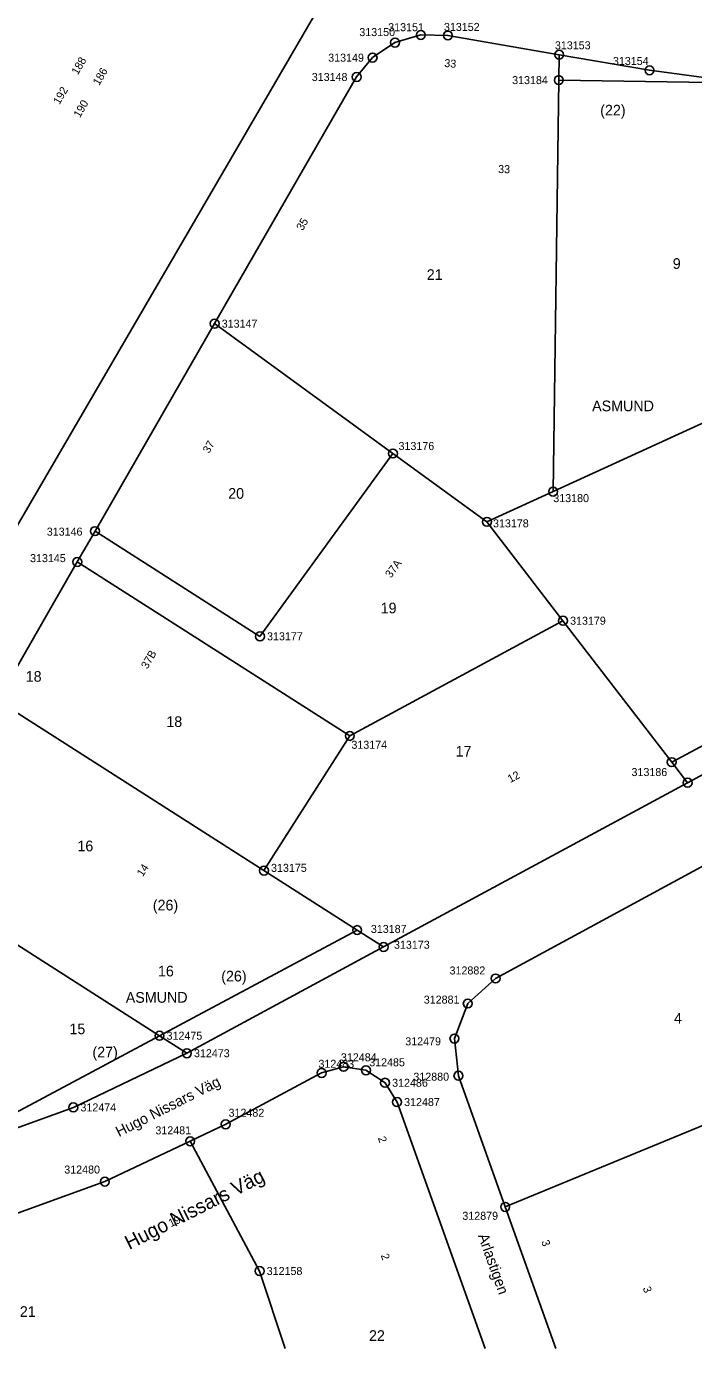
# Model space of a CAD drawing. Extents: x 141995 to 152570, y 6580184 to 6586000.
# Drawn here: x 142544.1 to 142619.1, y 6585000 to 6585148.7 of the extents above; entities that cross this region are included whole.
import ezdxf

# ---------------------------------------------------------------- set-up
doc = ezdxf.new("R2010")
doc.units = 0
for name, color, linetype in [('Level 10', 7, 'Continuous'), ('Level 40', 7, 'Continuous'), ('Level 42', 7, 'Continuous'), ('Level 43', 7, 'Continuous'), ('Level 5', 7, 'Continuous'), ('Level 50', 7, 'Continuous'), ('Level 51', 7, 'Continuous'), ('Level 52', 7, 'Continuous'), ('Level 53', 7, 'Continuous'), ('Level 54', 7, 'Continuous'), ('Level 55', 7, 'Continuous'), ('Level 58', 7, 'Continuous'), ('Level 59', 7, 'Continuous'), ('Level 6', 7, 'Continuous'), ('Level 60', 7, 'Continuous'), ('Level 7', 7, 'Continuous'), ('Level 9', 7, 'Continuous')]:
    doc.layers.add(name, color=color, linetype=linetype)

msp = doc.modelspace()

# ---------------------------------------------------------------- linework, layer by layer
at = {"layer": 'Level 10'}
for centre in [(142585.56, 6585146.87), (142588.47, 6585147.73), (142591.51, 6585147.67), (142583.04, 6585145.18), (142604.03, 6585145.51), (142614.19, 6585143.75), (142581.25, 6585143), (142603.99, 6585142.65), (142565.27, 6585115.26), (142585.33, 6585100.66), (142603.35, 6585096.37), (142551.82, 6585091.93), (142595.91, 6585092.97), (142549.82, 6585088.46), (142604.46, 6585081.85), (142570.37, 6585080.09), (142580.48, 6585068.9), (142616.69, 6585065.95), (142618.48, 6585063.63), (142570.82, 6585053.75), (142581.31, 6585047.06), (142584.28, 6585045.16), (142596.88, 6585041.62), (142593.75, 6585038.8), (142559.07, 6585035.18), (142592.25, 6585034.86), (142562.15, 6585033.21), (142577.31, 6585030.99), (142579.78, 6585031.69), (142582.3, 6585031.3), (142592.7, 6585030.68), (142584.44, 6585029.89), (142585.79, 6585027.72), (142549.38, 6585027.12), (142566.52, 6585025.22), (142562.52, 6585023.31), (142552.92, 6585018.77), (142597.96, 6585015.93), (142570.33, 6585008.72)]:
    msp.add_circle(centre, 0.5, dxfattribs=at)
at = {"layer": 'Level 5'}
for points in [[(142534.91, 6585078.61), (142586.48, 6585167.12)], [(142585.56, 6585146.87), (142588.47, 6585147.73)], [(142588.47, 6585147.73), (142591.51, 6585147.67)], [(142591.51, 6585147.67), (142604.03, 6585145.51)], [(142583.04, 6585145.18), (142585.56, 6585146.87)], [(142581.25, 6585143), (142583.04, 6585145.18)], [(142604.03, 6585145.51), (142603.99, 6585142.65)], [(142565.27, 6585115.26), (142581.25, 6585143)], [(142603.99, 6585142.65), (142630.81, 6585142.24)], [(142551.82, 6585091.93), (142565.27, 6585115.26)], [(142549.82, 6585088.46), (142551.82, 6585091.93)], [(142540.84, 6585072.88), (142549.82, 6585088.46)], [(142645.02, 6585081.08), (142616.69, 6585065.95)], [(142618.48, 6585063.63), (142616.69, 6585065.95)], [(142584.28, 6585045.16), (142618.48, 6585063.63)], [(142631.51, 6585060.39), (142596.88, 6585041.62)], [(142581.31, 6585047.06), (142559.07, 6585035.18)], [(142581.31, 6585047.06), (142584.28, 6585045.16)], [(142593.75, 6585038.8), (142596.88, 6585041.62)], [(142592.25, 6585034.86), (142593.75, 6585038.8)], [(142533.59, 6585021.58), (142559.07, 6585035.18)], [(142592.7, 6585030.68), (142592.25, 6585034.86)], [(142577.31, 6585030.99), (142579.78, 6585031.69)], [(142579.78, 6585031.69), (142582.3, 6585031.3)], [(142582.3, 6585031.3), (142584.44, 6585029.89)], [(142566.52, 6585025.22), (142577.31, 6585030.99)], [(142584.44, 6585029.89), (142585.79, 6585027.72)], [(142597.96, 6585015.93), (142592.7, 6585030.68)], [(142585.79, 6585027.72), (142595.69, 6585000)], [(142562.52, 6585023.31), (142566.52, 6585025.22)], [(142552.92, 6585018.77), (142562.52, 6585023.31)], [(142539.34, 6585013.87), (142552.92, 6585018.77)], [(142603.65, 6585000), (142597.96, 6585015.93)]]:
    msp.add_lwpolyline(points, dxfattribs=at)
at = {"layer": 'Level 6'}
for points in [[(142502.12, 6585000), (142502.91, 6585011.03), (142503.92, 6585018.86), (142505.8, 6585026.53), (142508.53, 6585033.94), (142512.08, 6585040.99), (142517.82, 6585050.94), (142527.3, 6585067.41), (142534.04, 6585079.1), (142534.91, 6585078.61), (142586.48, 6585167.12)], [(142622.24, 6585142.68), (142614.19, 6585143.75), (142604.03, 6585145.51), (142591.51, 6585147.67), (142588.47, 6585147.73), (142585.56, 6585146.87), (142583.04, 6585145.18), (142581.25, 6585143), (142565.27, 6585115.26), (142551.82, 6585091.93), (142549.82, 6585088.46), (142540.84, 6585072.88)], [(142535.89, 6585022.24), (142549.38, 6585027.12), (142562.15, 6585033.21), (142584.28, 6585045.16), (142618.48, 6585063.63), (142646.31, 6585078.66)], [(142638.01, 6585000), (142642.39, 6585034.25), (142645.03, 6585035.66), (142631.51, 6585060.39), (142596.88, 6585041.62), (142593.75, 6585038.8), (142592.25, 6585034.86), (142592.7, 6585030.68), (142597.96, 6585015.93), (142603.65, 6585000)], [(142595.69, 6585000), (142585.79, 6585027.72), (142584.44, 6585029.89), (142582.3, 6585031.3), (142579.78, 6585031.69), (142577.31, 6585030.99), (142566.52, 6585025.22), (142562.52, 6585023.31), (142552.92, 6585018.77), (142539.34, 6585013.87), (142538.75, 6585013.66), (142524.16, 6585009.97), (142519.14, 6585008.95), (142515.2, 6585007.22), (142512.36, 6585003.99), (142511.18, 6585000)]]:
    msp.add_lwpolyline(points, dxfattribs=at)
at = {"layer": 'Level 7'}
for points in [[(142603.99, 6585142.65), (142603.35, 6585096.37)], [(142565.27, 6585115.26), (142585.33, 6585100.66)], [(142630.24, 6585108.68), (142603.35, 6585096.37)], [(142585.33, 6585100.66), (142570.37, 6585080.09)], [(142585.33, 6585100.66), (142595.91, 6585092.97)], [(142603.35, 6585096.37), (142595.91, 6585092.97)], [(142595.91, 6585092.97), (142604.46, 6585081.85)], [(142570.37, 6585080.09), (142551.82, 6585091.93)], [(142549.82, 6585088.46), (142580.48, 6585068.9)], [(142604.46, 6585081.85), (142580.48, 6585068.9)], [(142616.69, 6585065.95), (142604.46, 6585081.85)], [(142540.84, 6585072.88), (142570.82, 6585053.75)], [(142580.48, 6585068.9), (142570.82, 6585053.75)], [(142529.86, 6585053.82), (142559.07, 6585035.18)], [(142570.82, 6585053.75), (142581.31, 6585047.06)], [(142642.39, 6585034.25), (142597.96, 6585015.93)], [(142562.52, 6585023.31), (142570.33, 6585008.72)], [(142570.33, 6585008.72), (142573.22, 6585000)]]:
    msp.add_lwpolyline(points, dxfattribs=at)
at = {"layer": 'Level 9'}
for points in [[(142618.48, 6585063.63), (142616.69, 6585065.95)], [(142581.31, 6585047.06), (142584.28, 6585045.16)], [(142559.07, 6585035.18), (142562.15, 6585033.21)]]:
    msp.add_lwpolyline(points, dxfattribs=at)

# ---------------------------------------------------------------- texts
at = {"layer": 'Level 40'}
msp.add_text('Hugo Nissars Väg', height=1.2, rotation=26.8813, dxfattribs=at).set_placement((142554.52, 6585023.77))
at = {"layer": 'Level 42'}
msp.add_text('Arlastigen', height=1.2, rotation=289.5959, dxfattribs=at).set_placement((142594.88, 6585012.69))
at = {"layer": 'Level 43'}
msp.add_text('Hugo Nissars Väg', height=1.6, rotation=26.8813, dxfattribs=at).set_placement((142555.68, 6585011.08))
at = {"layer": 'Level 50'}
msp.add_text('ASMUND', height=1.2, rotation=0.0514, dxfattribs=at).set_placement((142607.74, 6585105.41))
at = {"layer": 'Level 51'}
for s, p in [('9', (142616.81, 6585121.42)), ('21', (142589.14, 6585120.18)), ('20', (142566.8, 6585095.57)), ('19', (142583.95, 6585082.68)), ('18', (142559.84, 6585069.9)), ('16', (142549.84, 6585055.92)), ('4', (142616.95, 6585036.55)), ('22', (142582.64, 6585000.86))]:
    msp.add_text(s, height=1.2, rotation=0.0514, dxfattribs=at).set_placement(p)
msp.add_text('17', height=1.2, dxfattribs=at).set_placement((142592.38, 6585066.57))
at = {"layer": 'Level 52'}
for s, rotation, p in [('(22)', 0.0514, (142608.65, 6585138.67)), ('(26)', 0.1764, (142566.02, 6585041.28))]:
    msp.add_text(s, height=1.2, rotation=rotation, dxfattribs=at).set_placement(p)
at = {"layer": 'Level 53'}
for s, p in [('313151', (142584.8, 6585148.15)), ('313152', (142591.07, 6585148.18)), ('313150', (142581.55, 6585147.6)), ('313149', (142578.05, 6585144.72)), ('313153', (142603.55, 6585146.11)), ('313154', (142610.08, 6585144.35)), ('313148', (142576.2, 6585142.55)), ('313184', (142598.74, 6585142.2)), ('313147', (142566.07, 6585114.81)), ('313176', (142585.96, 6585101.05)), ('313180', (142603.37, 6585095.19)), ('313146', (142546.39, 6585091.42)), ('313178', (142596.59, 6585092.35)), ('313145', (142544.51, 6585088.44)), ('313179', (142605.26, 6585081.4)), ('313177', (142571.17, 6585079.65)), ('313174', (142580.66, 6585067.45)), ('313186', (142612.17, 6585064.38)), ('313175', (142571.62, 6585053.61)), ('313187', (142582.85, 6585046.74)), ('313173', (142585.45, 6585044.96)), ('312882', (142591.7, 6585042.07)), ('312881', (142588.8, 6585038.79)), ('312475', (142559.87, 6585034.73)), ('312479', (142586.72, 6585034.1)), ('312473', (142562.95, 6585032.76)), ('312484', (142579.48, 6585032.3)), ('312485', (142582.66, 6585031.74)), ('312483', (142576.95, 6585031.57)), ('312486', (142585.24, 6585029.44)), ('312880', (142587.63, 6585030.12)), ('312487', (142586.59, 6585027.27)), ('312474', (142550.18, 6585026.67)), ('312482', (142566.84, 6585026.07)), ('312481', (142558.61, 6585024.09)), ('312480', (142548.36, 6585019.68)), ('312879', (142593.14, 6585014.48)), ('312158', (142571.13, 6585008.27))]:
    msp.add_text(s, height=0.9, rotation=0.0514, dxfattribs=at).set_placement(p)
at = {"layer": 'Level 54'}
for s, rotation, p in [('188', 59.7716, (142549.88, 6585143.17)), ('186', 59.7716, (142552.28, 6585141.97)), ('192', 59.7716, (142547.81, 6585139.83)), ('190', 59.7716, (142550.11, 6585138.35)), ('33', 359.0823, (142597.16, 6585132.2)), ('37', 60.0476, (142564.65, 6585100.6)), ('37A', 53.9597, (142585.1, 6585086.58)), ('37B', 60.0456, (142557.71, 6585076.35)), ('12', 28.0983, (142598.53, 6585063.59)), ('14', 57.1296, (142557.19, 6585053)), ('19', 25.3614, (142560.35, 6585013.63)), ('2', 289.6399, (142583.95, 6585010.49)), ('3', 289.8329, (142613.42, 6585006.8))]:
    msp.add_text(s, height=0.9, rotation=rotation, dxfattribs=at).set_placement(p)
at = {"layer": 'Level 55'}
for s, rotation, p in [('33', 354.8793, (142591.08, 6585144.14)), ('35', 60.0506, (142575.18, 6585125.65)), ('2', 289.6399, (142583.62, 6585023.68)), ('3', 289.6439, (142602.01, 6585012.03))]:
    msp.add_text(s, height=0.9, rotation=rotation, dxfattribs=at).set_placement(p)
at = {"layer": 'Level 58'}
msp.add_text('ASMUND', height=1.2, rotation=0.1764, dxfattribs=at).set_placement((142555.28, 6585038.88))
at = {"layer": 'Level 59'}
for s, rotation, p in [('18', 0.0514, (142544.02, 6585074.99)), ('16', 0.1764, (142558.9, 6585041.85)), ('15', 0.1764, (142548.94, 6585035.35)), ('21', 0.0514, (142543.36, 6585003.56))]:
    msp.add_text(s, height=1.2, rotation=rotation, dxfattribs=at).set_placement(p)
at = {"layer": 'Level 60'}
for s, rotation, p in [('(26)', 0.0514, (142558.32, 6585049.27)), ('(27)', 0.1764, (142551.53, 6585032.74))]:
    msp.add_text(s, height=1.2, rotation=rotation, dxfattribs=at).set_placement(p)

doc.saveas('drawing.dxf')
